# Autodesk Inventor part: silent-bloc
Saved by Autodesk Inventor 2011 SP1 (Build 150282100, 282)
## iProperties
Created: 2010-12
Part Number: silent-bloc
Document SubType Name: Modeling
Designer: eric
Density: 1 g/cm^3
Author: eric
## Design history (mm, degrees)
feature "Base1"
node "Solide1"
node "Corps solides"
node "Corps surfaciques"
